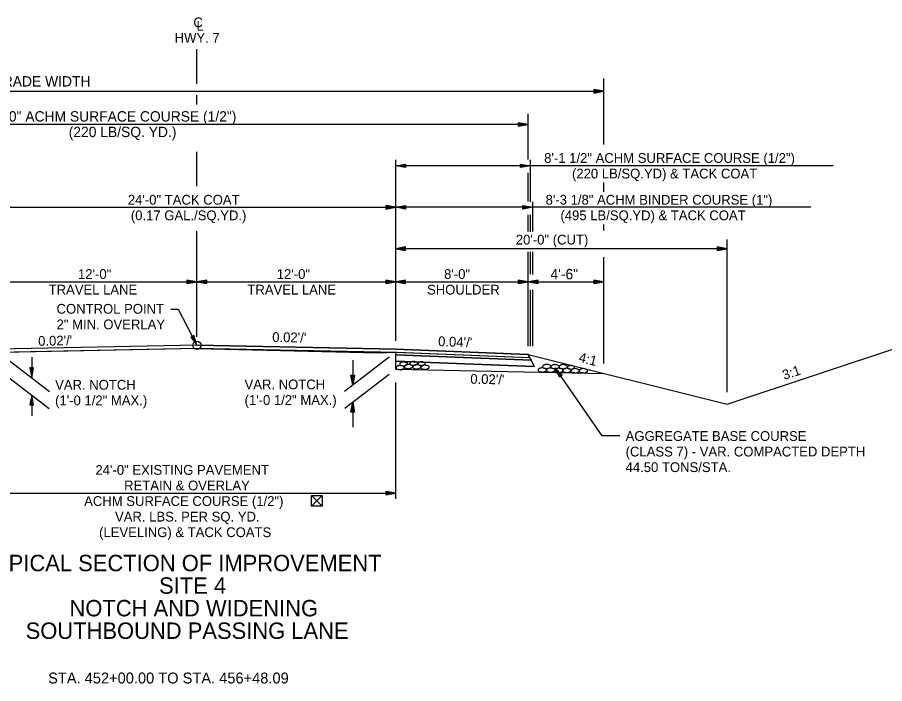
# Model space of a CAD drawing. Extents: x 1398183 to 1398373, y 1967240 to 1968889.
# Drawn here: x 1398245.9 to 1398298.2, y 1968016.7 to 1968056.9 of the extents above; entities that cross this region are included whole.
import ezdxf

# ---------------------------------------------------------------- set-up
doc = ezdxf.new("R2010")
doc.units = 0
for name, color, linetype in [('1', 7, 'Continuous'), ('10', 7, 'Continuous'), ('19', 7, 'Continuous'), ('42', 7, 'Continuous'), ('7', 7, 'Continuous'), ('Level 1', 7, 'Continuous'), ('Level 9', 7, 'Continuous')]:
    doc.layers.add(name, color=color, linetype=linetype)

# ---------------------------------------------------------------- blocks, each defined once
blk = doc.blocks.new('ROCKS')
at = {"layer": '1'}
blk.add_spline([(0.013, 0.06), (0.053, 0.053), (0.107, 0.033), (0.133, 0.013), (0.133, -0.007), (0.12, -0.033), (0.107, -0.04), (0.073, -0.053), (0.033, -0.067), (0.013, -0.067), (-0.02, -0.06), (-0.06, -0.053), (-0.087, -0.047), (-0.113, -0.02), (-0.113, -0.007), (-0.107, 0.02), (-0.087, 0.033), (-0.067, 0.047), (-0.033, 0.053), (-0.02, 0.06), (0.013, 0.06)], degree=3, dxfattribs=at)

msp = doc.modelspace()

# ---------------------------------------------------------------- linework, layer by layer
at = {"layer": '10'}
for p, q in [((1398264.285, 1968028.038), (1398263.644, 1968027.396)), ((1398263.644, 1968028.038), (1398264.285, 1968027.396)), ((1398263.904, 1968027.396), (1398263.893, 1968027.396))]:
    msp.add_line(p, q, dxfattribs=at)
msp.add_lwpolyline([(1398263.893, 1968027.396), (1398263.644, 1968027.396), (1398263.644, 1968028.038), (1398264.285, 1968028.038), (1398264.285, 1968027.396), (1398263.904, 1968027.396)], dxfattribs=at)
at = {"layer": '19'}
for p, q in [((1398281.284, 1968049.221), (1398281.284, 1968053.215)), ((1398221.989, 1968052.435), (1398281.284, 1968052.435)), ((1398280.684, 1968052.54), (1398280.684, 1968052.33)), ((1398281.284, 1968052.435), (1398280.684, 1968052.54)), ((1398281.124, 1968052.45), (1398280.684, 1968052.485)), ((1398280.684, 1968052.33), (1398281.284, 1968052.435)), ((1398280.684, 1968052.38), (1398281.124, 1968052.42)), ((1398276.719, 1968048.319), (1398276.719, 1968051.082)), ((1398276.119, 1968050.54), (1398276.119, 1968050.33)), ((1398276.719, 1968050.435), (1398276.119, 1968050.54)), ((1398276.719, 1968050.435), (1398226.719, 1968050.435)), ((1398276.559, 1968050.45), (1398276.119, 1968050.485)), ((1398276.119, 1968050.33), (1398276.719, 1968050.435)), ((1398276.119, 1968050.38), (1398276.559, 1968050.42)), ((1398268.719, 1968037.367), (1398268.719, 1968048.294)), ((1398268.719, 1968047.935), (1398269.319, 1968048.04)), ((1398295.125, 1968047.935), (1398268.719, 1968047.935)), ((1398269.319, 1968047.83), (1398268.719, 1968047.935)), ((1398268.879, 1968047.95), (1398269.319, 1968047.985)), ((1398269.319, 1968047.88), (1398268.879, 1968047.92)), ((1398269.319, 1968048.04), (1398269.319, 1968047.83)), ((1398276.248, 1968047.83), (1398276.248, 1968048.04)), ((1398276.248, 1968048.04), (1398276.848, 1968047.935)), ((1398276.248, 1968047.985), (1398276.688, 1968047.95)), ((1398276.848, 1968047.935), (1398276.248, 1968047.83)), ((1398276.688, 1968047.92), (1398276.248, 1968047.88)), ((1398276.848, 1968045.763), (1398276.848, 1968048.294)), ((1398276.719, 1968045.782), (1398276.719, 1968047.505)), ((1398281.284, 1968046.362), (1398281.284, 1968046.934)), ((1398215.924, 1968045.435), (1398268.719, 1968045.435)), ((1398268.119, 1968045.54), (1398268.119, 1968045.33)), ((1398268.719, 1968045.435), (1398268.119, 1968045.54)), ((1398268.559, 1968045.45), (1398268.119, 1968045.485)), ((1398268.119, 1968045.33), (1398268.719, 1968045.435)), ((1398268.119, 1968045.38), (1398268.559, 1968045.42)), ((1398268.719, 1968045.435), (1398269.319, 1968045.54)), ((1398293.768, 1968045.435), (1398268.719, 1968045.435)), ((1398269.319, 1968045.33), (1398268.719, 1968045.435)), ((1398268.879, 1968045.45), (1398269.319, 1968045.485)), ((1398269.319, 1968045.38), (1398268.879, 1968045.42)), ((1398269.319, 1968045.54), (1398269.319, 1968045.33)), ((1398276.387, 1968045.33), (1398276.387, 1968045.54)), ((1398276.387, 1968045.54), (1398276.987, 1968045.435)), ((1398276.387, 1968045.485), (1398276.827, 1968045.45)), ((1398276.987, 1968045.435), (1398276.387, 1968045.33)), ((1398276.827, 1968045.42), (1398276.387, 1968045.38)), ((1398276.987, 1968043.964), (1398276.987, 1968045.76)), ((1398276.719, 1968043.964), (1398276.719, 1968044.987)), ((1398276.848, 1968043.945), (1398276.848, 1968044.987)), ((1398281.284, 1968044.039), (1398281.284, 1968044.396)), ((1398288.719, 1968034.275), (1398288.719, 1968043.482)), ((1398269.319, 1968043.04), (1398268.719, 1968042.935)), ((1398288.719, 1968042.935), (1398268.719, 1968042.935)), ((1398268.719, 1968042.935), (1398269.319, 1968042.83)), ((1398269.319, 1968042.985), (1398268.879, 1968042.95)), ((1398268.879, 1968042.92), (1398269.319, 1968042.88)), ((1398269.319, 1968042.83), (1398269.319, 1968043.04)), ((1398276.719, 1968037.047), (1398276.719, 1968042.752)), ((1398276.848, 1968041.408), (1398276.848, 1968042.752)), ((1398276.987, 1968041.37), (1398276.987, 1968042.752)), ((1398288.119, 1968043.04), (1398288.119, 1968042.83)), ((1398288.719, 1968042.935), (1398288.119, 1968043.04)), ((1398288.559, 1968042.95), (1398288.119, 1968042.985)), ((1398288.119, 1968042.83), (1398288.719, 1968042.935)), ((1398288.119, 1968042.88), (1398288.559, 1968042.92)), ((1398281.284, 1968036), (1398281.284, 1968042.42)), ((1398244.719, 1968040.935), (1398256.719, 1968040.935)), ((1398256.119, 1968041.04), (1398256.119, 1968040.83)), ((1398256.719, 1968040.935), (1398256.119, 1968041.04)), ((1398256.559, 1968040.95), (1398256.119, 1968040.985)), ((1398256.119, 1968040.83), (1398256.719, 1968040.935)), ((1398256.119, 1968040.88), (1398256.559, 1968040.92)), ((1398257.319, 1968041.04), (1398256.719, 1968040.935)), ((1398256.719, 1968040.935), (1398257.319, 1968040.83)), ((1398256.719, 1968040.935), (1398268.719, 1968040.935)), ((1398257.319, 1968040.985), (1398256.879, 1968040.95)), ((1398256.879, 1968040.92), (1398257.319, 1968040.88)), ((1398257.319, 1968040.83), (1398257.319, 1968041.04)), ((1398268.119, 1968041.04), (1398268.119, 1968040.83)), ((1398268.719, 1968040.935), (1398268.119, 1968041.04)), ((1398268.559, 1968040.95), (1398268.119, 1968040.985)), ((1398268.119, 1968040.83), (1398268.719, 1968040.935)), ((1398268.119, 1968040.88), (1398268.559, 1968040.92)), ((1398269.319, 1968041.04), (1398268.719, 1968040.935)), ((1398268.719, 1968040.935), (1398269.319, 1968040.83)), ((1398268.719, 1968040.935), (1398276.719, 1968040.935)), ((1398269.319, 1968040.985), (1398268.879, 1968040.95)), ((1398268.879, 1968040.92), (1398269.319, 1968040.88)), ((1398269.319, 1968040.83), (1398269.319, 1968041.04)), ((1398276.119, 1968041.04), (1398276.119, 1968040.83)), ((1398276.719, 1968040.935), (1398276.119, 1968041.04)), ((1398276.559, 1968040.95), (1398276.119, 1968040.985)), ((1398276.119, 1968040.83), (1398276.719, 1968040.935)), ((1398276.119, 1968040.88), (1398276.559, 1968040.92)), ((1398277.319, 1968041.04), (1398276.719, 1968040.935)), ((1398276.719, 1968040.935), (1398281.284, 1968040.935)), ((1398276.719, 1968040.935), (1398277.319, 1968040.83)), ((1398277.319, 1968040.985), (1398276.879, 1968040.95)), ((1398276.879, 1968040.92), (1398277.319, 1968040.88)), ((1398277.319, 1968040.83), (1398277.319, 1968041.04)), ((1398280.684, 1968041.04), (1398280.684, 1968040.83)), ((1398281.284, 1968040.935), (1398280.684, 1968041.04)), ((1398281.124, 1968040.95), (1398280.684, 1968040.985)), ((1398280.684, 1968040.83), (1398281.284, 1968040.935)), ((1398280.684, 1968040.88), (1398281.124, 1968040.92)), ((1398276.848, 1968037.047), (1398276.848, 1968040.461)), ((1398276.987, 1968037.047), (1398276.987, 1968040.461)), ((1398256.542, 1968037.69), (1398256.356, 1968037.595)), ((1398256.356, 1968037.595), (1398256.719, 1968037.107)), ((1398256.398, 1968037.613), (1398256.633, 1968037.244)), ((1398256.657, 1968037.254), (1398256.496, 1968037.661)), ((1398256.719, 1968037.107), (1398256.542, 1968037.69)), ((1398256.719, 1968037.107), (1398268.719, 1968036.867)), ((1398288.719, 1968033.547), (1398299.559, 1968037.161)), ((1398245.116, 1968036.397), (1398247.818, 1968034.328)), ((1398246.748, 1968036.398), (1398246.748, 1968035.148)), ((1398268.322, 1968036.397), (1398265.62, 1968034.328)), ((1398268.719, 1968036.867), (1398276.719, 1968036.547)), ((1398268.719, 1968035.657), (1398268.719, 1968036.699)), ((1398268.719, 1968036.157), (1398268.719, 1968036.532)), ((1398268.719, 1968036.532), (1398268.719, 1968036.532)), ((1398268.719, 1968036.532), (1398268.719, 1968036.532)), ((1398276.719, 1968036.547), (1398288.719, 1968033.547)), ((1398276.719, 1968036.547), (1398276.804, 1968036.377)), ((1398276.806, 1968036.376), (1398276.891, 1968036.205)), ((1398266.122, 1968036.212), (1398266.122, 1968034.712)), ((1398277.082, 1968035.823), (1398268.719, 1968036.157)), ((1398268.719, 1968036.157), (1398268.719, 1968036.157)), ((1398276.891, 1968036.205), (1398277.082, 1968035.823)), ((1398245.116, 1968035.354), (1398247.798, 1968033.301)), ((1398246.853, 1968035.748), (1398246.643, 1968035.748)), ((1398246.643, 1968035.748), (1398246.748, 1968035.148)), ((1398246.698, 1968035.748), (1398246.733, 1968035.308)), ((1398246.748, 1968035.148), (1398246.853, 1968035.748)), ((1398246.763, 1968035.308), (1398246.803, 1968035.748)), ((1398268.322, 1968035.353), (1398265.64, 1968033.301)), ((1398266.017, 1968035.312), (1398266.227, 1968035.312)), ((1398266.122, 1968034.712), (1398266.017, 1968035.312)), ((1398266.107, 1968034.872), (1398266.067, 1968035.312)), ((1398266.227, 1968035.312), (1398266.122, 1968034.712)), ((1398266.172, 1968035.312), (1398266.137, 1968034.872)), ((1398268.719, 1968035.657), (1398281.284, 1968035.406)), ((1398281.175, 1968031.646), (1398278.344, 1968035.742)), ((1398278.597, 1968035.19), (1398278.344, 1968035.742)), ((1398278.344, 1968035.742), (1398278.77, 1968035.307)), ((1398278.638, 1968035.218), (1398278.421, 1968035.602)), ((1398278.444, 1968035.618), (1398278.725, 1968035.279)), ((1398278.77, 1968035.307), (1398278.597, 1968035.19)), ((1398268.719, 1968027.834), (1398268.719, 1968034.867)), ((1398246.748, 1968034.105), (1398246.643, 1968033.505)), ((1398246.733, 1968033.945), (1398246.698, 1968033.505)), ((1398246.853, 1968033.505), (1398246.748, 1968034.105)), ((1398246.748, 1968034.105), (1398246.748, 1968032.855)), ((1398246.803, 1968033.505), (1398246.763, 1968033.945)), ((1398246.643, 1968033.505), (1398246.853, 1968033.505)), ((1398266.017, 1968033.069), (1398266.122, 1968033.669)), ((1398266.067, 1968033.069), (1398266.107, 1968033.509)), ((1398266.122, 1968033.669), (1398266.227, 1968033.069)), ((1398266.122, 1968033.669), (1398266.122, 1968032.169)), ((1398266.137, 1968033.509), (1398266.172, 1968033.069)), ((1398266.227, 1968033.069), (1398266.017, 1968033.069)), ((1398282.241, 1968031.646), (1398281.175, 1968031.646)), ((1398244.719, 1968028.184), (1398268.719, 1968028.184)), ((1398268.119, 1968028.289), (1398268.119, 1968028.079)), ((1398268.719, 1968028.184), (1398268.119, 1968028.289)), ((1398268.559, 1968028.199), (1398268.119, 1968028.234)), ((1398268.119, 1968028.079), (1398268.719, 1968028.184)), ((1398268.119, 1968028.129), (1398268.559, 1968028.169))]:
    msp.add_line(p, q, dxfattribs=at)
for points in [[(1398255.139, 1968039.284), (1398255.585, 1968039.284), (1398256.718, 1968037.107)], [(1398226.634, 1968036.217), (1398232.634, 1968036.457), (1398256.719, 1968036.941), (1398268.804, 1968036.697), (1398276.804, 1968036.377)], [(1398256.719, 1968037.107), (1398244.719, 1968036.867), (1398232.719, 1968036.627)], [(1398268.719, 1968036.532), (1398276.891, 1968036.205)], [(1398268.719, 1968036.532), (1398276.891, 1968036.205), (1398277.082, 1968035.823)], [(1398268.719, 1968036.157), (1398277.082, 1968035.823)]]:
    msp.add_lwpolyline(points, dxfattribs=at)
for points in [[(1398226.634, 1968036.217), (1398232.634, 1968036.457), (1398256.719, 1968036.941), (1398268.804, 1968036.697), (1398276.804, 1968036.377), (1398276.719, 1968036.547), (1398268.719, 1968036.867), (1398256.719, 1968037.107), (1398232.719, 1968036.627), (1398226.719, 1968036.387)], [(1398276.804, 1968036.377), (1398276.891, 1968036.205), (1398268.719, 1968036.532), (1398268.719, 1968036.699)]]:
    msp.add_lwpolyline(points, close=True, dxfattribs=at)
at = {"layer": '42'}
for points in [[(1398256.726, 1968036.904), (1398245.032, 1968036.679), (1398244.719, 1968036.7)], [(1398256.726, 1968036.904), (1398267.628, 1968036.65), (1398268.719, 1968036.699)]]:
    msp.add_lwpolyline(points, dxfattribs=at)
at = {"layer": '7'}
for p, q in [((1398256.72, 1968052.886), (1398256.721, 1968054.973)), ((1398256.719, 1968051.629), (1398256.719, 1968052.208)), ((1398256.719, 1968046.716), (1398256.719, 1968048.782)), ((1398256.719, 1968037.607), (1398256.719, 1968043.986))]:
    msp.add_line(p, q, dxfattribs=at)
at = {"layer": 'Level 9'}
msp.add_circle((1398256.719, 1968037.107), 0.25, dxfattribs=at)

# ---------------------------------------------------------------- block references
at = {"layer": 'Level 1'}
for p, xscale, yscale, rotation in [((1398268.969, 1968035.767), 2.011654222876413, 2.011654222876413, 1.8263814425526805), ((1398269.181, 1968035.987), 1.8866375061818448, 1.886637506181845, 1.8263814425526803), ((1398269.477, 1968035.83), 2.011654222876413, 2.011654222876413, 1.8263814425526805), ((1398269.789, 1968036.022), 1.851115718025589, 1.851115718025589, 1.8263814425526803), ((1398269.971, 1968035.811), 2.011654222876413, 2.011654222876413, 1.8263814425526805), ((1398270.264, 1968036.009), 1.773922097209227, 1.773922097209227, 1.8263814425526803), ((1398270.469, 1968035.786), 2.011654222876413, 2.011654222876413, 1.8263814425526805), ((1398277.817, 1968035.832), 2.011654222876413, 2.0116542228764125, -0.17361855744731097), ((1398278.317, 1968035.82), 2.011654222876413, 2.0116542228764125, -0.17361855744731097), ((1398278.813, 1968035.82), 2.011654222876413, 2.0116542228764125, -0.17361855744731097), ((1398279.275, 1968035.781), 1.7335100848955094, 1.7335100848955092, -0.173618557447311), ((1398277.547, 1968035.625), 2.011654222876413, 2.0116542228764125, -0.17361855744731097), ((1398278.051, 1968035.615), 2.011654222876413, 2.0116542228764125, -0.17361855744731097), ((1398278.543, 1968035.597), 2.011654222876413, 2.0116542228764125, -0.17361855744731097), ((1398279.033, 1968035.597), 2.011654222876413, 2.0116542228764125, -0.17361855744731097), ((1398279.527, 1968035.577), 2.011654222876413, 2.0116542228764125, -0.17361855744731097), ((1398280.029, 1968035.577), 2.011654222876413, 2.0116542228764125, -0.17361855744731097)]:
    msp.add_blockref('ROCKS', p, dxfattribs=dict(at, xscale=xscale, yscale=yscale, rotation=rotation))

# ---------------------------------------------------------------- texts
at = {"layer": '10'}
for s, height, p in [('20\'-0" (CUT)', 0.59001, (1398275.969, 1968043.187)), ('12\'-0"', 0.59, (1398249.541, 1968041.11)), ('12\'-0"', 0.59, (1398261.541, 1968041.11)), ('8\'-0"', 0.59, (1398271.639, 1968041.11)), ('TRAVEL LANE', 0.59001, (1398247.769, 1968040.17)), ('TRAVEL LANE', 0.59001, (1398259.769, 1968040.17)), ('SHOULDER', 0.59, (1398270.612, 1968040.17)), ('CONTROL POINT', 0.59001, (1398248.248, 1968039.012)), ('2" MIN. OVERLAY', 0.59001, (1398248.248, 1968038.072)), ('VAR. NOTCH', 0.59, (1398248.161, 1968034.428)), ('VAR. NOTCH', 0.59, (1398259.596, 1968034.45)), ('(1\'-0 1/2" MAX.)', 0.59001, (1398248.161, 1968033.488)), ('(1\'-0 1/2" MAX.)', 0.59001, (1398259.596, 1968033.51))]:
    msp.add_text(s, height=height, dxfattribs=at).set_placement(p)
for s, height, rotation, p in [("0.04'/'", 0.59, 357.7094, (1398271.269, 1968037.061)), ('4:1', 0.59, 345.9638, (1398279.722, 1968036.117)), ('3:1', 0.59, 18.4349, (1398292.172, 1968035.009)), ('24\'-0" EXISTING PAVEMENT', 0.59001, 0, (1398250.595, 1968029.292)), ('RETAIN & OVERLAY', 0.59001, 0, (1398252.326, 1968028.352)), ('ACHM SURFACE COURSE (1/2")', 0.59001, 0, (1398249.915, 1968027.412)), ('VAR. LBS. PER SQ. YD.', 0.59001, 0, (1398251.777, 1968026.472)), ('(LEVELING) & TACK COATS', 0.59001, 0, (1398250.816, 1968025.532))]:
    msp.add_text(s, height=height, rotation=rotation, dxfattribs=at).set_placement(p)
at = {"layer": '19'}
for s, height, p in [('C', 0.59, (1398256.507, 1968056.296)), ('L', 0.59, (1398256.696, 1968056.086)), ('HWY. 7', 0.59, (1398255.376, 1968055.366)), ('59\'-3" SUBGRADE WIDTH', 0.625, (1398240.27, 1968052.722)), ('50\'-0" ACHM SURFACE COURSE (1/2")', 0.625, (1398244.001, 1968050.607)), ('(220 LB/SQ. YD.)', 0.625, (1398248.981, 1968049.669)), ('4\'-6"', 0.625, (1398278.065, 1968041.093)), ('TYPICAL SECTION OF IMPROVEMENT', 0.98999, (1398243.666, 1968023.474)), ('SITE 4', 0.99, (1398254.435, 1968022.113)), ('NOTCH AND WIDENING', 0.98999, (1398249.029, 1968020.751)), ('SOUTHBOUND PASSING LANE', 0.98999, (1398246.383, 1968019.39)), ('STA. 452+00.00 TO STA. 456+48.09', 0.65999, (1398247.739, 1968016.699))]:
    msp.add_text(s, height=height, dxfattribs=at).set_placement(p)
for s, height, rotation, p in [("0.02'/'", 0.59, 1.1458, (1398247.141, 1968037.072)), ("0.02'/'", 0.59, 358.8542, (1398261.262, 1968037.312)), ("0.02'/'", 0.59, 358.8542, (1398273.217, 1968034.787)), ('AGGREGATE BASE COURSE', 0.59001, 360, (1398282.598, 1968031.337)), ('(CLASS 7) - VAR. COMPACTED DEPTH', 0.59001, 360, (1398282.598, 1968030.397)), ('44.50 TONS/STA.', 0.59001, 360, (1398282.598, 1968029.457))]:
    msp.add_text(s, height=height, rotation=rotation, dxfattribs=at).set_placement(p)
at = {"layer": '42'}
for s, p in [('8\'-1 1/2" ACHM SURFACE COURSE (1/2")', (1398277.681, 1968048.114)), ('(220 LB/SQ.YD) & TACK COAT', (1398279.361, 1968047.174)), ('24\'-0" TACK COAT', (1398252.55, 1968045.593)), ('8\'-3 1/8" ACHM BINDER COURSE (1")', (1398277.768, 1968045.593)), ('(0.17 GAL./SQ.YD.)', (1398252.733, 1968044.653)), ('(495 LB/SQ.YD) & TACK COAT', (1398278.663, 1968044.653))]:
    msp.add_text(s, height=0.59001, rotation=360, dxfattribs=at).set_placement(p)

doc.saveas('drawing.dxf')
